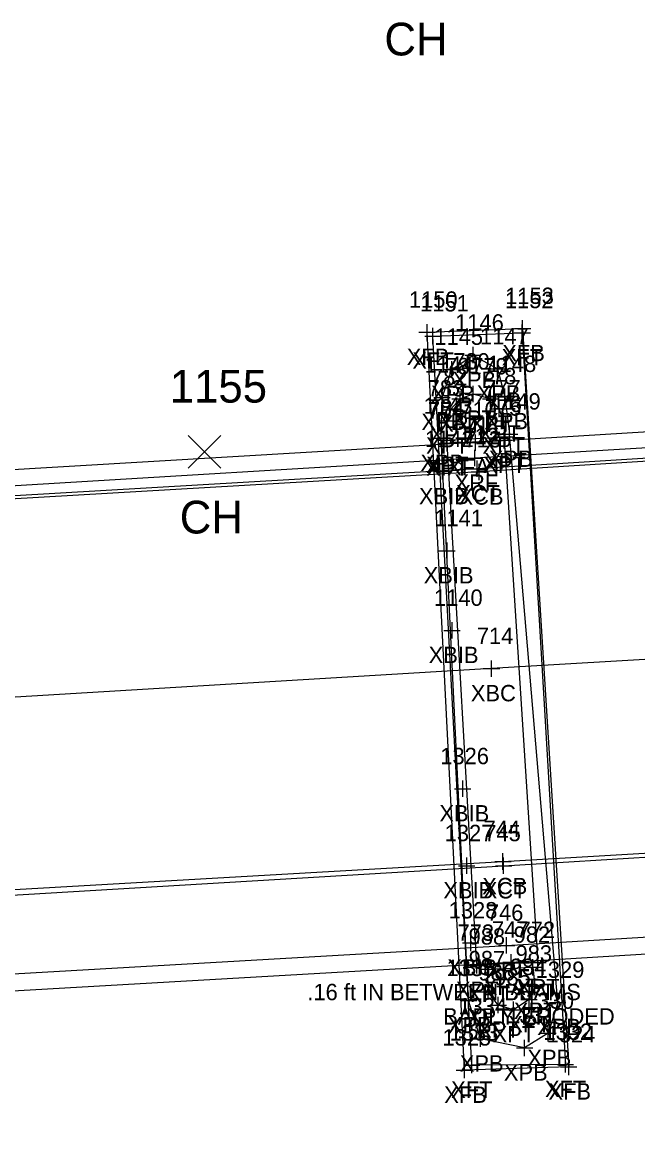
# Model space of a CAD drawing. Extents: x 1716490 to 1717645, y 888034 to 890004.
# Drawn here: x 1717028.9 to 1717066.5, y 888212.7 to 888280.6 of the extents above; entities that cross this region are included whole.
import ezdxf

# ---------------------------------------------------------------- set-up
doc = ezdxf.new("R2010")
doc.units = 0
for name, color, linetype in [('B_A', 7, 'Continuous'), ('B_C', 7, 'Continuous'), ('B_I', 7, 'Continuous'), ('B_TIC', 7, 'Continuous'), ('BDC', 7, 'Continuous'), ('BELB', 7, 'Continuous'), ('BF', 7, 'Continuous'), ('BFT', 7, 'Continuous'), ('BR', 7, 'Continuous'), ('BSUBM', 7, 'Continuous'), ('L_A', 7, 'Continuous'), ('L_I', 7, 'Continuous'), ('L_TIC', 7, 'Continuous')]:
    doc.layers.add(name, color=color, linetype=linetype)

msp = doc.modelspace()

# ---------------------------------------------------------------- linework, layer by layer
at = {"layer": 'B_TIC'}
for p, q in [((1717053.643, 888261.69), (1717053.719, 888261.69)), ((1717059.463, 888261.66), (1717059.539, 888261.66)), ((1717059.483, 888261.92), (1717059.559, 888261.92)), ((1717054.003, 888261.46), (1717054.079, 888261.46)), ((1717056.453, 888260.29), (1717056.529, 888260.29)), ((1717055.153, 888259.42), (1717055.229, 888259.42)), ((1717057.943, 888259.45), (1717058.019, 888259.45)), ((1717054.563, 888257.71), (1717054.639, 888257.71)), ((1717055.66, 888257.616), (1717055.735, 888257.616)), ((1717056.466, 888257.912), (1717056.542, 888257.912)), ((1717057.53, 888257.612), (1717057.606, 888257.612)), ((1717058.403, 888257.76), (1717058.479, 888257.76)), ((1717055.066, 888256.946), (1717055.142, 888256.946)), ((1717058.048, 888257.007), (1717058.123, 888257.007)), ((1717054.864, 888256.266), (1717054.939, 888256.266)), ((1717058.314, 888256.276), (1717058.39, 888256.276)), ((1717058.683, 888255.46), (1717058.759, 888255.46)), ((1717054.503, 888255.21), (1717054.579, 888255.21)), ((1717054.865, 888255.093), (1717054.94, 888255.093)), ((1717054.872, 888254.916), (1717054.948, 888254.916)), ((1717056.613, 888254.944), (1717056.689, 888254.944)), ((1717058.355, 888255.088), (1717058.431, 888255.088)), ((1717058.418, 888255.305), (1717058.494, 888255.305)), ((1717056.561, 888253.997), (1717056.636, 888253.997)), ((1717054.581, 888253.178), (1717054.657, 888253.178)), ((1717056.704, 888253.344), (1717056.779, 888253.344)), ((1717056.833, 888253.148), (1717056.909, 888253.148)), ((1717054.866, 888248.335), (1717054.942, 888248.335)), ((1717055.175, 888243.464), (1717055.25, 888243.464)), ((1717057.584, 888241.128), (1717057.659, 888241.128)), ((1717055.828, 888233.783), (1717055.904, 888233.783)), ((1717056.069, 888229.078), (1717056.144, 888229.078)), ((1717058.282, 888229.335), (1717058.357, 888229.335)), ((1717058.325, 888229.074), (1717058.4, 888229.074)), ((1717056.313, 888224.355), (1717056.388, 888224.355)), ((1717058.508, 888224.208), (1717058.583, 888224.208)), ((1717056.691, 888222.99), (1717056.767, 888222.99)), ((1717058.793, 888223.18), (1717058.869, 888223.18)), ((1717060.118, 888222.867), (1717060.193, 888222.867)), ((1717060.418, 888223.157), (1717060.494, 888223.157)), ((1717057.366, 888222.754), (1717057.441, 888222.754)), ((1717060.234, 888221.711), (1717060.31, 888221.711)), ((1717056.178, 888220.83), (1717056.254, 888220.83)), ((1717057.37, 888221.368), (1717057.446, 888221.368)), ((1717059.884, 888220.895), (1717059.959, 888220.895)), ((1717057.989, 888220.559), (1717058.065, 888220.559)), ((1717058.935, 888220.27), (1717059.011, 888220.27)), ((1717061.634, 888220.72), (1717061.709, 888220.72)), ((1717061.042, 888218.831), (1717061.118, 888218.831)), ((1717056.908, 888218.495), (1717056.984, 888218.495)), ((1717059.602, 888217.938), (1717059.677, 888217.938)), ((1717056.372, 888216.887), (1717056.447, 888216.887)), ((1717062.103, 888216.93), (1717062.179, 888216.93)), ((1717062.303, 888216.78), (1717062.379, 888216.78)), ((1717055.933, 888216.58), (1717056.009, 888216.58))]:
    msp.add_line(p, q, dxfattribs=at)
for points in [[(1717059.48, 888261.42), (1717059.48, 888262.42)], [(1717053.14, 888261.69), (1717054.14, 888261.69)], [(1717053.64, 888261.19), (1717053.64, 888262.19)], [(1717054, 888260.96), (1717054, 888261.96)], [(1717058.96, 888261.66), (1717059.96, 888261.66)], [(1717058.98, 888261.92), (1717059.98, 888261.92)], [(1717059.46, 888261.16), (1717059.46, 888262.16)], [(1717053.5, 888261.46), (1717054.5, 888261.46)], [(1717055.95, 888260.29), (1717056.95, 888260.29)], [(1717056.45, 888259.79), (1717056.45, 888260.79)], [(1717055.15, 888258.92), (1717055.15, 888259.92)], [(1717057.94, 888258.95), (1717057.94, 888259.95)], [(1717054.65, 888259.42), (1717055.65, 888259.42)], [(1717057.44, 888259.45), (1717058.44, 888259.45)], [(1717054.56, 888257.21), (1717054.56, 888258.21)], [(1717056.463, 888257.412), (1717056.463, 888258.412)], [(1717058.4, 888257.26), (1717058.4, 888258.26)], [(1717054.06, 888257.71), (1717055.06, 888257.71)], [(1717055.156, 888257.616), (1717056.156, 888257.616)], [(1717055.656, 888257.116), (1717055.656, 888258.116)], [(1717055.963, 888257.912), (1717056.963, 888257.912)], [(1717057.027, 888257.612), (1717058.027, 888257.612)], [(1717057.527, 888257.112), (1717057.527, 888258.112)], [(1717057.9, 888257.76), (1717058.9, 888257.76)], [(1717058.044, 888256.507), (1717058.044, 888257.507)], [(1717054.563, 888256.946), (1717055.563, 888256.946)], [(1717055.063, 888256.446), (1717055.063, 888257.446)], [(1717057.544, 888257.007), (1717058.544, 888257.007)], [(1717054.36, 888256.266), (1717055.36, 888256.266)], [(1717054.86, 888255.766), (1717054.86, 888256.766)], [(1717057.811, 888256.276), (1717058.811, 888256.276)], [(1717058.311, 888255.776), (1717058.311, 888256.776)], [(1717054.5, 888254.71), (1717054.5, 888255.71)], [(1717054.861, 888254.593), (1717054.861, 888255.593)], [(1717058.18, 888255.46), (1717059.18, 888255.46)], [(1717058.352, 888254.588), (1717058.352, 888255.588)], [(1717058.415, 888254.805), (1717058.415, 888255.805)], [(1717058.68, 888254.96), (1717058.68, 888255.96)], [(1717054, 888255.21), (1717055, 888255.21)], [(1717054.361, 888255.093), (1717055.361, 888255.093)], [(1717054.369, 888254.916), (1717055.369, 888254.916)], [(1717054.869, 888254.416), (1717054.869, 888255.416)], [(1717056.11, 888254.944), (1717057.11, 888254.944)], [(1717056.61, 888254.444), (1717056.61, 888255.444)], [(1717057.852, 888255.088), (1717058.852, 888255.088)], [(1717057.915, 888255.305), (1717058.915, 888255.305)], [(1717056.557, 888253.497), (1717056.557, 888254.497)], [(1717054.578, 888252.678), (1717054.578, 888253.678)], [(1717056.057, 888253.997), (1717057.057, 888253.997)], [(1717056.7, 888252.844), (1717056.7, 888253.844)], [(1717056.83, 888252.648), (1717056.83, 888253.648)], [(1717054.078, 888253.178), (1717055.078, 888253.178)], [(1717056.2, 888253.344), (1717057.2, 888253.344)], [(1717056.33, 888253.148), (1717057.33, 888253.148)], [(1717054.863, 888247.835), (1717054.863, 888248.835)], [(1717054.363, 888248.335), (1717055.363, 888248.335)], [(1717055.171, 888242.964), (1717055.171, 888243.964)], [(1717054.671, 888243.464), (1717055.671, 888243.464)], [(1717057.58, 888240.628), (1717057.58, 888241.628)], [(1717057.08, 888241.128), (1717058.08, 888241.128)], [(1717055.325, 888233.783), (1717056.325, 888233.783)], [(1717055.825, 888233.283), (1717055.825, 888234.283)], [(1717058.278, 888228.835), (1717058.278, 888229.835)], [(1717055.565, 888229.078), (1717056.565, 888229.078)], [(1717056.065, 888228.578), (1717056.065, 888229.578)], [(1717057.778, 888229.335), (1717058.778, 888229.335)], [(1717057.821, 888229.074), (1717058.821, 888229.074)], [(1717058.321, 888228.574), (1717058.321, 888229.574)], [(1717055.809, 888224.355), (1717056.809, 888224.355)], [(1717056.309, 888223.855), (1717056.309, 888224.855)], [(1717058.004, 888224.208), (1717059.004, 888224.208)], [(1717058.504, 888223.708), (1717058.504, 888224.708)], [(1717058.79, 888222.68), (1717058.79, 888223.68)], [(1717060.415, 888222.657), (1717060.415, 888223.657)], [(1717056.188, 888222.99), (1717057.188, 888222.99)], [(1717056.688, 888222.49), (1717056.688, 888223.49)], [(1717057.362, 888222.254), (1717057.362, 888223.254)], [(1717058.29, 888223.18), (1717059.29, 888223.18)], [(1717059.614, 888222.867), (1717060.614, 888222.867)], [(1717059.915, 888223.157), (1717060.915, 888223.157)], [(1717060.114, 888222.367), (1717060.114, 888223.367)], [(1717056.862, 888222.754), (1717057.862, 888222.754)], [(1717060.231, 888221.211), (1717060.231, 888222.211)], [(1717057.367, 888220.868), (1717057.367, 888221.868)], [(1717059.731, 888221.711), (1717060.731, 888221.711)], [(1717055.675, 888220.83), (1717056.675, 888220.83)], [(1717056.175, 888220.33), (1717056.175, 888221.33)], [(1717056.867, 888221.368), (1717057.867, 888221.368)], [(1717057.986, 888220.059), (1717057.986, 888221.059)], [(1717059.38, 888220.895), (1717060.38, 888220.895)], [(1717059.88, 888220.395), (1717059.88, 888221.395)], [(1717061.63, 888220.22), (1717061.63, 888221.22)], [(1717057.486, 888220.559), (1717058.486, 888220.559)], [(1717058.432, 888220.27), (1717059.432, 888220.27)], [(1717058.932, 888219.77), (1717058.932, 888220.77)], [(1717061.13, 888220.72), (1717062.13, 888220.72)], [(1717056.905, 888217.995), (1717056.905, 888218.995)], [(1717060.539, 888218.831), (1717061.539, 888218.831)], [(1717061.039, 888218.331), (1717061.039, 888219.331)], [(1717056.405, 888218.495), (1717057.405, 888218.495)], [(1717059.598, 888217.438), (1717059.598, 888218.438)], [(1717059.098, 888217.938), (1717060.098, 888217.938)], [(1717062.1, 888216.43), (1717062.1, 888217.43)], [(1717055.868, 888216.887), (1717056.868, 888216.887)], [(1717055.93, 888216.08), (1717055.93, 888217.08)], [(1717056.368, 888216.387), (1717056.368, 888217.387)], [(1717061.6, 888216.93), (1717062.6, 888216.93)], [(1717061.8, 888216.78), (1717062.8, 888216.78)], [(1717062.3, 888216.28), (1717062.3, 888217.28)], [(1717055.43, 888216.58), (1717056.43, 888216.58)]]:
    msp.add_lwpolyline(points, dxfattribs=at)
at = {"layer": 'BDC'}
for points in [[(1717176.589, 888262.234), (1717176.877, 888260.812), (1717116.829, 888257.088), (1717056.7, 888253.344), (1716997.03, 888249.858), (1716936.998, 888246.313), (1716877.496, 888242.928), (1716877.301, 888244.49)], [(1717176.976, 888262.024), (1717176.866, 888260.514), (1717116.827, 888256.946), (1717056.83, 888253.148), (1716997.002, 888249.663), (1716937.062, 888246.095), (1716877.423, 888242.56)], [(1716878.76, 888218.785), (1716938.254, 888222.245), (1716997.847, 888225.861), (1717058.278, 888229.335), (1717118.147, 888232.862), (1717177.913, 888236.497)], [(1716878.985, 888212.69), (1716878.754, 888218.609), (1716938.217, 888221.984), (1716998.215, 888225.489), (1717058.321, 888229.074), (1717118.074, 888232.734), (1717177.978, 888236.214), (1717178.104, 888235.65), (1717178.633, 888230.445)]]:
    msp.add_lwpolyline(points, dxfattribs=at)
at = {"layer": 'BELB'}
msp.add_lwpolyline([(1717176.82, 888248.242), (1717117.599, 888244.664), (1717057.58, 888241.128), (1716997.658, 888237.527), (1716937.868, 888233.85), (1716878.264, 888230.514)], dxfattribs=at)
at = {"layer": 'BF'}
for points in [[(1717176.589, 888262.234), (1717116.538, 888258.636), (1717056.61, 888254.944), (1716996.925, 888251.433), (1716937.102, 888247.945), (1716877.301, 888244.49)], [(1716878.985, 888212.69), (1716938.928, 888216.097), (1716998.537, 888219.726), (1717058.79, 888223.18), (1717118.388, 888226.857), (1717178.633, 888230.445)]]:
    msp.add_lwpolyline(points, dxfattribs=at)
at = {"layer": 'BFT'}
for points in [[(1717053.64, 888261.69), (1717059.48, 888261.92), (1717062.3, 888216.78), (1717055.93, 888216.58)], [(1717055.93, 888216.58), (1717053.64, 888261.69)], [(1717054, 888261.46), (1717059.46, 888261.66), (1717062.1, 888216.93), (1717056.368, 888216.887)], [(1717056.368, 888216.887), (1717054, 888261.46)]]:
    msp.add_lwpolyline(points, dxfattribs=at)
at = {"layer": 'BR'}
for points in [[(1717175.997, 888261.982), (1717175.88, 888261.141), (1717117.062, 888257.612), (1717056.557, 888253.997), (1716997.021, 888250.409), (1716936.966, 888246.784), (1716878.141, 888243.386), (1716877.962, 888244.411)], [(1716879.623, 888212.902), (1716879.679, 888213.775), (1716938.703, 888217.127), (1716998.522, 888220.762), (1717058.504, 888224.208), (1717118.654, 888227.867), (1717177.581, 888231.531), (1717177.859, 888230.636)]]:
    msp.add_lwpolyline(points, dxfattribs=at)
at = {"layer": 'BSUBM'}
for points in [[(1717054.5, 888255.21), (1717054.56, 888257.71), (1717055.15, 888259.42), (1717056.45, 888260.29), (1717057.94, 888259.45), (1717058.4, 888257.76), (1717058.68, 888255.46)], [(1717058.415, 888255.305), (1717058.311, 888256.276), (1717058.044, 888257.007), (1717057.527, 888257.612), (1717056.463, 888257.912), (1717055.656, 888257.616), (1717055.063, 888256.946), (1717054.86, 888256.266), (1717054.861, 888255.093)], [(1717061.63, 888220.72), (1717058.68, 888255.46)], [(1717056.175, 888220.83), (1717054.5, 888255.21)], [(1717054.861, 888255.093), (1717058.415, 888255.305)], [(1717060.415, 888223.157), (1717056.688, 888222.99), (1717054.869, 888254.916), (1717058.352, 888255.088)], [(1717058.352, 888255.088), (1717060.415, 888223.157)], [(1717060.114, 888222.867), (1717060.231, 888221.711), (1717059.88, 888220.895), (1717058.932, 888220.27), (1717057.986, 888220.559), (1717057.367, 888221.368), (1717057.362, 888222.754)], [(1717057.362, 888222.754), (1717060.114, 888222.867)], [(1717061.63, 888220.72), (1717061.039, 888218.831), (1717059.598, 888217.938), (1717056.905, 888218.495), (1717056.175, 888220.83)]]:
    msp.add_lwpolyline(points, dxfattribs=at)
at = {"layer": 'L_TIC'}
for points in [[(1717039.039, 888253.388), (1717041.039, 888255.388)], [(1717041.039, 888253.388), (1717039.039, 888255.388)]]:
    msp.add_lwpolyline(points, dxfattribs=at)

# ---------------------------------------------------------------- texts
at = {"layer": 'B_A'}
for s, p in [('XFB', (1717058.24, 888259.92)), ('XFB', (1717052.4, 888259.69)), ('XFT', (1717052.744, 888259.46)), ('XFT', (1717058.204, 888259.66)), ('XPB', (1717055.186, 888258.29)), ('XPB', (1717053.886, 888257.42)), ('XPB', (1717056.676, 888257.45)), ('XPT', (1717055.183, 888255.912)), ('XPB', (1717053.296, 888255.71)), ('XPT', (1717054.377, 888255.616)), ('XPT', (1717056.247, 888255.612)), ('XPB', (1717057.136, 888255.76)), ('XPT', (1717053.783, 888254.946)), ('XPT', (1717056.765, 888255.007)), ('XPT', (1717053.581, 888254.266)), ('XPT', (1717057.031, 888254.276)), ('XPB', (1717053.236, 888253.21)), ('XPT', (1717057.135, 888253.305)), ('XPB', (1717057.416, 888253.46)), ('XPT', (1717053.582, 888253.093)), ('XPT', (1717053.589, 888252.916)), ('XFAT', (1717054.866, 888252.944)), ('XPT', (1717057.072, 888253.088)), ('XRF', (1717055.317, 888251.997)), ('XBIB', (1717053.149, 888251.178)), ('XCT', (1717055.421, 888251.344)), ('XCB', (1717055.566, 888251.148)), ('XBIB', (1717053.434, 888246.335)), ('XBIB', (1717053.742, 888241.464)), ('XBC', (1717056.317, 888239.128)), ('XBIB', (1717054.396, 888231.783)), ('XCB', (1717057.014, 888227.335)), ('XBIB', (1717054.636, 888227.078)), ('XCT', (1717057.042, 888227.074)), ('XBIB', (1717054.88, 888222.355)), ('XRF', (1717057.264, 888222.208)), ('XFAT', (1717057.046, 888221.18)), ('XPT', (1717059.135, 888221.157)), ('XPT', (1717055.408, 888220.99)), ('XPT', (1717056.083, 888220.754)), ('XPT', (1717058.835, 888220.867)), ('XPT', (1717056.087, 888219.368)), ('XPT', (1717058.951, 888219.711)), ('XPB', (1717054.911, 888218.83)), ('XPT', (1717056.706, 888218.559)), ('XPT', (1717058.601, 888218.895)), ('XPB', (1717060.366, 888218.72)), ('XPT', (1717057.652, 888218.27)), ('XPB', (1717055.641, 888216.495)), ('XPB', (1717059.775, 888216.831)), ('XPB', (1717058.335, 888215.938)), ('XFB', (1717054.69, 888214.58)), ('XFT', (1717055.112, 888214.887)), ('XFT', (1717060.844, 888214.93)), ('XFB', (1717061.06, 888214.78))]:
    msp.add_text(s, height=1, dxfattribs=at).set_placement(p)
at = {"layer": 'B_C'}
for s, p in [('.16 ft IN BETWEEN BEAMS', (1717046.325, 888220.855)), ('BADLY ERODED', (1717054.63, 888219.367))]:
    msp.add_text(s, height=1, dxfattribs=at).set_placement(p)
at = {"layer": 'B_I'}
for s, p in [('1153', (1717058.417, 888263.42)), ('1150', (1717052.534, 888263.19)), ('1151', (1717053.22, 888262.96)), ('1152', (1717058.397, 888263.16)), ('1146', (1717055.359, 888261.79)), ('1145', (1717054.087, 888260.92)), ('1147', (1717056.877, 888260.95)), ('1144', (1717053.497, 888259.21)), ('780', (1717055.238, 888259.412)), ('1148', (1717057.337, 888259.26)), ('781', (1717054.759, 888259.116)), ('779', (1717056.342, 888259.112)), ('782', (1717053.882, 888258.446)), ('778', (1717056.863, 888258.507)), ('783', (1717053.679, 888257.766)), ('777', (1717057.13, 888257.776)), ('1143', (1717053.437, 888256.71)), ('784', (1717053.68, 888256.593)), ('775', (1717057.171, 888256.588)), ('776', (1717057.206, 888256.805)), ('1149', (1717057.613, 888256.96)), ('774', (1717053.688, 888256.416)), ('710', (1717055.669, 888256.444)), ('711', (1717055.943, 888255.497)), ('1142', (1717053.515, 888254.678)), ('712', (1717055.803, 888254.844)), ('713', (1717055.932, 888254.648)), ('1141', (1717054.083, 888249.835)), ('1140', (1717054.065, 888244.964)), ('714', (1717056.683, 888242.628)), ('1326', (1717054.451, 888235.283)), ('744', (1717057.097, 888230.835)), ('1327', (1717054.719, 888230.578)), ('745', (1717057.14, 888230.574)), ('1328', (1717054.963, 888225.855)), ('746', (1717057.296, 888225.708)), ('747', (1717057.609, 888224.68)), ('772', (1717059.234, 888224.657)), ('773', (1717055.507, 888224.49)), ('988', (1717056.181, 888224.254)), ('982', (1717058.933, 888224.367)), ('983', (1717059.049, 888223.211)), ('987', (1717056.186, 888222.868)), ('1335', (1717054.828, 888222.33)), ('986', (1717056.777, 888222.059)), ('984', (1717058.699, 888222.395)), ('1329', (1717060.28, 888222.22)), ('985', (1717057.751, 888221.77)), ('1334', (1717055.558, 888219.995)), ('1330', (1717059.649, 888220.331)), ('1331', (1717058.535, 888219.438)), ('1332', (1717060.754, 888218.43)), ('1325', (1717054.584, 888218.08)), ('1333', (1717055.022, 888218.387)), ('1324', (1717060.954, 888218.28))]:
    msp.add_text(s, height=1, dxfattribs=at).set_placement(p)
at = {"layer": 'L_A'}
for p in [(1717051.033, 888278.613), (1717038.527, 888249.388)]:
    msp.add_text('CH', height=2, dxfattribs=at).set_placement(p)
at = {"layer": 'L_I'}
msp.add_text('1155', height=2, dxfattribs=at).set_placement((1717037.913, 888257.388))

doc.saveas('drawing.dxf')
